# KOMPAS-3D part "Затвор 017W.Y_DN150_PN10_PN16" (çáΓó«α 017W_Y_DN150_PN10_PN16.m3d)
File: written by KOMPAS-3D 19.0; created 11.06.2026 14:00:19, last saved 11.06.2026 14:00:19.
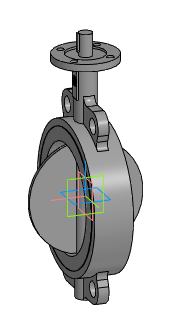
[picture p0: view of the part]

Document properties: Автор: Евгений; Полное имя файла: Z:\3.Личные\kachalov\001_3d для проектировщиков\x.x Тип 017W.Y(S) Затвор дисковый поворотный межфланцевый\_stp_Затвор 017W.Y_DN50-DN350\Затвор 017W_Y_DN150_PN10_PN16.m3d

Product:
- Part/product: Затвор 017W.Y_DN150_PN10_PN16

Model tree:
1. Операция без истории:1  (labels: Затвор 017W.Y_DN150_PN10_PN16)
